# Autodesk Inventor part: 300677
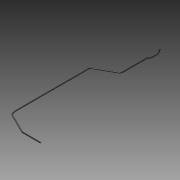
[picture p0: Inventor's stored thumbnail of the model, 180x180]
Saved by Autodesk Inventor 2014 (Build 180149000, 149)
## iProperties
Created: 2007-11
Part Number: 300677
Document SubType Name: Modeling
Designer: TH
Density: 8.08 g/cm^3
Mass: 81.1085 g
Surface Area: 92.7417 cm^2
Volume: 10.0382 cm^3
Material: Stainless Steel
Description: RIGHT BACK WIRE
Appearance: Dark Gray
Component Category: Back Component
Author: TH
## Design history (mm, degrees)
sketch "Sketch3"
  geometry: L1 (0, 96.6)-(0, -579.6) reference; L2 (0, -483)-(0, -197.68); L3 (4.08, -190.707)-(72.42, -152.293); L4 (76.5, -145.32)-(76.5, -51); A1 r 8 centre (8, -197.68) between (4.08, -190.707) and (0, -197.68); A2 r 8 centre (68.5, -145.32) between (72.42, -152.293) and (76.5, -145.32); 3 further points
  constraints: 6 end point, 6 point on line, 4 point on circle, 4 tangent, 2 centre point, 1 equal radius, 1 parallel
  dimensions: "d0" = 193 distance of point (0, 0) point (0, -193); "d1" = 43 vertical distance of point (76.5, -150) point (0, -193); "d2" = 99 distance of point (76.5, -150) L4.end; "d3" = 76.5 distance between parallel lines of L1 L4; "d4" = 290 distance of L2.start point (0, -193); "d5" = 8 radius of A1
workplane "Work Plane1"
sketch "Sketch4"
  geometry: C1 r 2.172 at (0, 0); 1 further point
  constraints: 1 centre point, 1 coincident
  dimensions: "d6" = 4.3434 diameter of C1
sweep "Sweep1" sketch "Sketch4" dims "d7" = 0
workplane "Work Plane2"
  workaxis "Work Axis7"
sketch "Sketch5"
  geometry: L1 (105.659, -5.928)-(96.32, -0.536); L2 (109.659, -7)-(133.397, -7); L3 (140.325, -3)-(145.266, 5.557); L4 (94.32, 2.172)-(94.32, -2.172) reference; L5 (94.32, 0)-(94.32, -4); A1 r 4 centre (94.32, -4) between (96.32, -0.536) and (94.32, 0); A2 r 8 centre (109.659, 1) between (105.659, -5.928) and (109.659, -7); A3 r 8 centre (133.397, 1) between (133.397, -7) and (140.325, -3); 3 further points
  constraints: 8 end point, 6 point on circle, 5 tangent, 4 point on line, 3 centre point, 1 coincident, 1 collinear, 1 equal radius, 1 midpoint, 1 perpendicular
  dimensions: "d10" = 4 distance of L5.start L5.end; "d11" = 60 deg angle of L1 L5; "d12" = 7 distance from line of L5.start L2; "d13" = 60 deg angle of L2 L3; "d14" = 30.5 distance of point (107.516, -7) point (138.016, -7); "d15" = 14.5 distance of point (138.016, -7) L3.end; "d16" = 8 radius of A2
sketch "Sketch6"
  geometry: C1 r 2.172 at (0, 0) reference; 1 further point
sweep "Sweep2" sketch "Sketch5", "Sketch6" dims "d17" = 0
workaxis "Work Axis8"
workplane "Work Plane3"
sketch "Sketch7"
  geometry: L1 (0, 2.172)-(0, -2.172) reference; L2 (0, 0)-(0, -4); L3 (-7.167, -4.793)-(-2.571, -0.936); A1 r 4 centre (0, -4) between (0, 0) and (-2.571, -0.936); 1 further point
  constraints: 4 end point, 2 point on circle, 1 centre point, 1 coincident, 1 midpoint, 1 point on line, 1 tangent
  dimensions: "d19" = 8 diameter of A1; "d21" = 6 distance of L3.start L3.end; "d22" = 50 deg angle of L3 L2
sketch "Sketch8"
  geometry: C1 r 2.172 at (0, 0) reference
sweep "Sweep3" sketch "Sketch7", "Sketch8" dims "d23" = 0
workplane "Work Plane4"
  workaxis "Work Axis9"
sketch "Sketch9"
  geometry: L1 (6, 2.172)-(6, -2.172) reference; L2 (6, 0)-(6, 4); L3 (28.618, 57.402)-(9.782, 2.698); A1 r 4 centre (6, 4) between (6, 0) and (9.782, 2.698); 1 further point
  constraints: 4 end point, 2 point on circle, 1 centre point, 1 coincident, 1 collinear, 1 midpoint, 1 tangent
  dimensions: "d25" = 4 distance of L2.start L2.end; "d26" = 19 deg angle of L3 L1
sketch "Sketch10"
  geometry: C1 r 2.172 at (0, 0) reference; 1 further point
sweep "Sweep4" sketch "Sketch9", "Sketch10" dims "d31" = 0
workplane "Work Plane5"
  workaxis "Work Axis10"
sketch "Sketch12"
  geometry: L1 (57.856, 2.172)-(57.856, -2.172) reference; L2 (57.856, 0)-(57.856, 4); L3 (122.287, 31.654)-(59.641, 0.42); A1 r 4 centre (57.856, 4) between (57.856, 0) and (59.641, 0.42); 1 further point
  constraints: 4 end point, 2 point on circle, 1 centre point, 1 coincident, 1 collinear, 1 midpoint, 1 tangent
  dimensions: "d39" = 4 distance of L2.start L2.end; "d40" = 70 distance of L3.start L3.end; "d41" = 63.5 deg angle of L1 L3
sketch "Sketch13"
  geometry: C1 r 2.172 at (0, 0) reference; 1 further point
sweep "Sweep5" sketch "Sketch12", "Sketch13" dims "d42" = 0
workaxis "Work Axis11"
workplane "Work Plane6"
workplane "Work Plane7"
body "Solid1"
other parameters: "d8" = 0, "d24" = 90 deg, "d34" = 10 deg, "d38" = 3.03687, "d43" = 0, "d44" = 90 deg
